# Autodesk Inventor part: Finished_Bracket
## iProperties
Created: 2004-06
Part Number: Finished_Bracket
Document SubType Name: Sheet Metal
Designer: rak
Manufacturer: Standard
Standards Organization: Custom
Author: rak
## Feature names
1. Hole1
2. Corner Round1
3. Plate1
4. Bend1
5. Plate2
6. Bend2
